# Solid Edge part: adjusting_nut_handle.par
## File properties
Title: Adjusting nut handle
Author: Abhinav Rai
Template: Normal.par
Last saved by: SOFT
Revision: 27
Application: Solid Edge
Accuracy: 0.99
Material: aluminum
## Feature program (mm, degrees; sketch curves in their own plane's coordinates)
sketch for "unnamed Protrusion 1" plane through (0, 0, 0) normal (0, -1, 0) x-axis (1, 0, 0)
  circle centre (0, 0) radius 9.5123
extrude "unnamed Protrusion 1" add finite 127 symmetric
chamfer "Chamfer_1" setback 1.5748
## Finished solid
Body 1: solid body, 5 faces, 4 edges, 0 vertices.
  Faces by surface: cone 2, plane 2, cylinder 1
  Edges by curve: circle 4
Bounding box of the edges (mm): 19.025 x 127.000 x 19.025, from (-9.5123, -63.5, -9.5123) to (9.5123, 63.5, 9.5123).
Cylindrical faces by radius (mm): R9.5123 x1
Conical faces (half-angle, radius in mm at the cone's reference point): 45 deg R7.9375 x1, 45 deg R9.5123 x1
Planar faces by outward normal: +y 1, -y 1
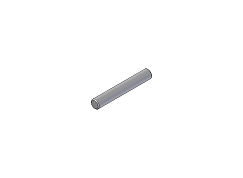
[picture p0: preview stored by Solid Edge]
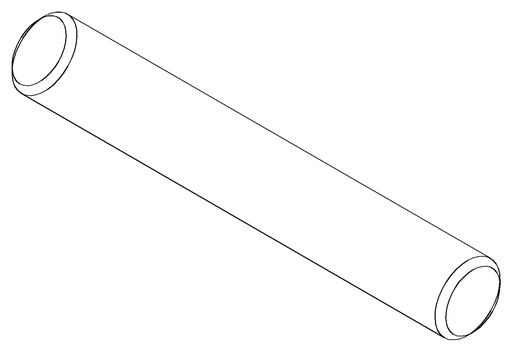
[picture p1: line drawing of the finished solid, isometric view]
